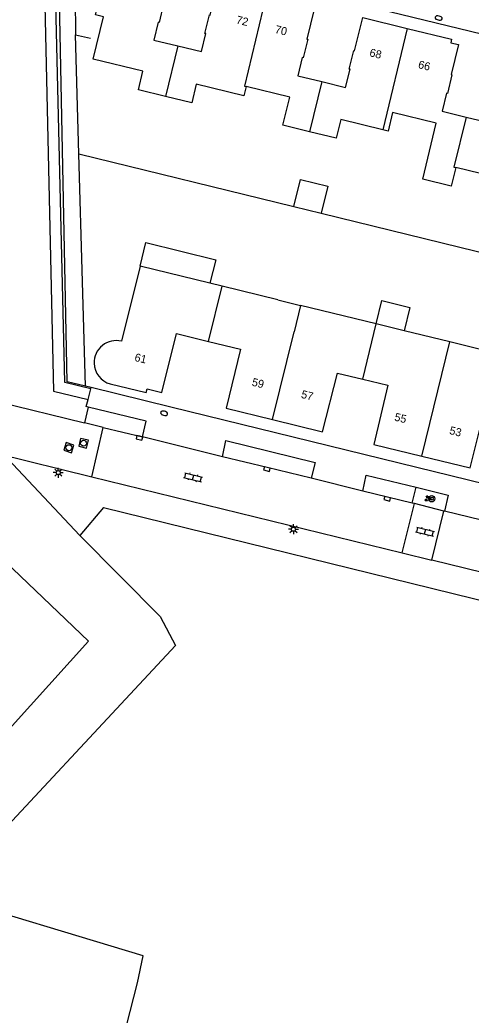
# Model space of a CAD drawing. Extents: x 125000 to 129004, y 397500 to 399008.
# Drawn here: x 126409.7 to 126466.2, y 397880.8 to 398005.2 of the extents above; entities that cross this region are included whole.
import ezdxf

# ---------------------------------------------------------------- set-up
doc = ezdxf.new("R2010")
doc.units = 0
for name, color, linetype in [('gg-afsc-erfafscheiding', 7, 'Continuous'), ('gg-anno-huisnummerreeks BGT', 7, 'Continuous'), ('gg-bbg-hoofdgebouw', 7, 'Continuous'), ('gg-bbg-luifel en loopbrug', 7, 'Continuous'), ('gg-bbg-tussenscheiding', 7, 'Continuous'), ('gg-knt-bronhoudergrens', 7, 'Continuous'), ('gg-knt-plantopografie kant verharding', 7, 'Continuous'), ('gg-knt-verharding', 7, 'Continuous'), ('gg-knt-verharding nz', 7, 'Continuous'), ('gt-grn-groengrens', 7, 'Continuous'), ('gt-grn-vlakafsluiter', 7, 'Continuous'), ('gt-symb-boom', 7, 'Continuous'), ('gt-symb-brandkraan', 7, 'Continuous'), ('gt-symb-groenvak', 7, 'Continuous'), ('gt-symb-klinker verharding', 7, 'Continuous'), ('gt-symb-kolk', 7, 'Continuous'), ('gt-symb-lichtmast', 7, 'Continuous'), ('gt-symb-rioolschacht', 7, 'Continuous')]:
    doc.layers.add(name, color=color, linetype=linetype)

# ---------------------------------------------------------------- blocks, each defined once
blk = doc.blocks.new('gt0-BR')
at = {"layer": 'gt-symb-brandkraan'}
for centre, radius, start, end in [((-0.24, 0), 0.206, 107.5669, 252.4331), ((0.6, -2.66), 3, 106.892, 107.5669), ((0, -0.69), 0.938, 73.108, 106.892), ((-0.6, -2.66), 3, 72.4331, 73.108), ((0.24, 0), 0.206, 287.567, 72.4331), ((0.6, 2.66), 3, 252.4331, 253.108), ((0, 0.69), 0.938, 253.108, 286.8921), ((-0.6, 2.66), 3, 286.8921, 287.567)]:
    blk.add_arc(centre, radius, start, end, dxfattribs=at)
blk = doc.blocks.new('gt0-RS')
at = {"layer": 'gt-symb-rioolschacht'}
blk.add_lwpolyline([(-0.5, -0.5), (0.5, -0.5), (0.5, 0.5), (-0.5, 0.5)], close=True, dxfattribs=at)
blk.add_circle((0, 0), 0.375, dxfattribs=at)
blk = doc.blocks.new('gt0-KOLK')
at = {"layer": 'gt-symb-kolk'}
blk.add_lwpolyline([(0, 0), (0.37, 0), (0.37, 0.4), (-0.38, 0.4), (-0.38, 0), (0, 0)], dxfattribs=at)
blk = doc.blocks.new('gt0-KL1')
at = {"layer": 'gt-symb-klinker verharding'}
for p, q in [((-1.15, 0.3), (1.15, 0.3)), ((-1, -0.3), (-1, 0.3)), ((-0.5, 0.3), (-0.5, 0.45)), ((0, -0.3), (0, 0.3)), ((0.5, 0.3), (0.5, 0.45)), ((1, -0.3), (1, 0.3)), ((-1.15, -0.3), (1.15, -0.3)), ((-0.5, -0.45), (-0.5, -0.3)), ((0.5, -0.45), (0.5, -0.3))]:
    blk.add_line(p, q, dxfattribs=at)
blk = doc.blocks.new('gt0-LMAST')
at = {"layer": 'gt-symb-lichtmast'}
for p, q in [((-0.18, 0.17), (-0.45, 0.44)), ((-0.01, 0.25), (-0.01, 0.62)), ((0.17, 0.17), (0.44, 0.44)), ((-0.26, 0), (-0.63, 0)), ((-0.18, -0.18), (-0.45, -0.45)), ((-0.01, -0.25), (-0.01, -0.63)), ((0.44, -0.45), (0.17, -0.18)), ((0.24, 0), (0.62, 0))]:
    blk.add_line(p, q, dxfattribs=at)
blk.add_circle((-0.01, 0), 0.25, dxfattribs=at)
blk = doc.blocks.new('gt0-GRVAK')
at = {"layer": 'gt-symb-groenvak'}
for p, q in [((-0.11, 0.19), (-0.23, 0.24)), ((-0.18, 0.15), (0.09, 0.15)), ((-0.09, 0.21), (-0.16, 0.32)), ((-0.05, 0.21), (-0.05, 0.39)), ((0, 0.21), (0.06, 0.32)), ((0.01, 0.19), (0.13, 0.24)), ((0.26, -0.05), (0.2, 0.06)), ((0.3, -0.05), (0.3, 0.13)), ((0.35, -0.05), (0.41, 0.06)), ((-0.24, -0.23), (-0.36, -0.18)), ((-0.32, -0.26), (-0.05, -0.26)), ((-0.23, -0.21), (-0.29, -0.09)), ((-0.18, -0.2), (-0.18, -0.02)), ((-0.14, -0.21), (-0.07, -0.09)), ((-0.12, -0.23), (0, -0.18)), ((0.24, -0.07), (0.12, -0.02)), ((0.17, -0.11), (0.44, -0.11)), ((0.37, -0.07), (0.49, -0.02))]:
    blk.add_line(p, q, dxfattribs=at)
blk = doc.blocks.new('gt0-BOOM')
at = {"layer": 'gt-symb-boom'}
for radius in [0.4, 0.2]:
    blk.add_circle((0, 0), radius, dxfattribs=at)

msp = doc.modelspace()

# ---------------------------------------------------------------- linework, layer by layer
at = {"layer": 'gg-afsc-erfafscheiding'}
for p, q in [((126417.11, 397988.44), (126416.68, 398003.33)), ((126416.68, 398003.33), (126418.55, 398002.89)), ((126417.11, 397988.44), (126444.02, 397981.86)), ((126447.42, 397981.02), (126484.77, 397971.88))]:
    msp.add_line(p, q, dxfattribs=at)
msp.add_lwpolyline([(126417.92, 397959.4), (126417.54, 397972.46), (126417.11, 397988.44)], dxfattribs=at)
at = {"layer": 'gg-bbg-hoofdgebouw'}
for p, q in [((126438.02, 397996.85), (126437.73, 397995.68)), ((126464.27, 397986.73), (126463.68, 397984.41)), ((126424.77, 397974.42), (126422.45, 397965.02)), ((126433.51, 397972.28), (126424.77, 397974.42)), ((126435.03, 397971.91), (126433.51, 397972.28)), ((126441.99, 397970.21), (126435.03, 397971.91)), ((126441.99, 397970.21), (126444.85, 397969.5)), ((126454.32, 397967.18), (126444.85, 397969.5)), ((126457.81, 397966.33), (126454.32, 397967.18)), ((126463.51, 397964.93), (126457.81, 397966.33)), ((126472.66, 397962.69), (126463.51, 397964.93))]:
    msp.add_line(p, q, dxfattribs=at)
for points in [[(126427.94, 397995.6), (126424.55, 397996.43), (126425.1, 397998.76), (126418.9, 398000.28), (126420.2, 398005.57), (126419.18, 398005.82), (126420.18, 398009.85), (126421.21, 398009.6), (126421.91, 398012.52), (126423.26, 398012.2), (126423.36, 398012.62), (126428.6, 398011.35), (126427.6, 398007.21), (126427.7, 398007.18), (126427.15, 398004.87), (126427.04, 398004.89), (126426.5, 398002.65), (126429.47, 398001.93)], [(126429.47, 398001.93), (126432.44, 398001.21), (126432.98, 398003.47), (126432.87, 398003.49), (126433.43, 398005.8), (126433.54, 398005.77), (126434.43, 398009.48), (126435.41, 398009.25), (126435.52, 398009.68), (126440.6, 398008.43)], [(126440.6, 398008.43), (126445.68, 398007.19), (126445.57, 398006.77), (126446.54, 398006.53), (126445.63, 398002.79), (126445.74, 398002.76), (126445.17, 398000.44), (126445.06, 398000.46), (126444.51, 397998.2), (126447.5, 397997.47)], [(126447.5, 397997.47), (126450.48, 397996.74), (126451.04, 397999), (126450.93, 397999.03), (126451.5, 398001.34), (126451.6, 398001.32), (126452.62, 398005.48), (126458.18, 398004.12)], [(126458.18, 398004.12), (126463.74, 398002.76), (126463.64, 398002.33), (126464.6, 398002.09), (126463.68, 397998.34), (126463.79, 397998.31), (126463.22, 397995.99), (126463.11, 397996.02), (126462.56, 397993.76), (126465.55, 397993.03)], [(126465.55, 397993.03), (126468.55, 397992.3), (126469.1, 397994.55), (126468.99, 397994.57), (126469.56, 397996.9), (126469.67, 397996.88), (126470.58, 398000.63), (126471.55, 398000.39), (126471.65, 398000.82), (126476.73, 397999.58)], [(126437.73, 397995.68), (126431.8, 397997.13), (126431.23, 397994.8), (126427.94, 397995.6)], [(126445.98, 397991.19), (126442.64, 397992.01), (126443.49, 397995.51), (126438.02, 397996.85)], [(126463.68, 397984.41), (126460.13, 397985.28), (126461.83, 397992.26), (126456.36, 397993.6), (126455.79, 397991.27), (126455.12, 397991.43)], [(126455.12, 397991.43), (126449.87, 397992.71), (126449.3, 397990.38), (126445.98, 397991.19)], [(126473.88, 397986.85), (126467.93, 397988.3), (126467.36, 397985.97), (126464.27, 397986.73)], [(126421.01, 397959.68), (126425.52, 397958.61), (126425.64, 397959.09), (126427.5, 397958.63), (126429.33, 397965.97), (126433.33, 397964.99)], [(126433.33, 397964.99), (126437.34, 397964.02), (126435.54, 397956.65), (126441.34, 397955.23)], [(126441.34, 397955.23), (126447.6, 397953.68), (126449.46, 397961.03), (126452.62, 397960.27)], [(126452.62, 397960.27), (126455.78, 397959.51), (126454.01, 397952.13), (126460.01, 397950.67)], [(126460.01, 397950.67), (126466.06, 397949.18), (126467.9, 397956.52), (126470.96, 397955.78)]]:
    msp.add_lwpolyline(points, dxfattribs=at)
for start, end in [(75.9037, 181.6433), (181.6226, 254.075)]:
    msp.add_arc((126421.77, 397962.34), 2.76, start, end, dxfattribs=at)
at = {"layer": 'gg-bbg-luifel en loopbrug'}
msp.add_line((126444.02, 397981.86), (126447.42, 397981.02), dxfattribs=at)
for points in [[(126444.02, 397981.86), (126444.84, 397985.24), (126448.24, 397984.42), (126447.42, 397981.02)], [(126424.77, 397974.42), (126425.48, 397977.34), (126434.23, 397975.2), (126433.51, 397972.28)], [(126454.32, 397967.18), (126455.03, 397970.1), (126458.53, 397969.24), (126457.81, 397966.33)]]:
    msp.add_lwpolyline(points, dxfattribs=at)
at = {"layer": 'gg-bbg-tussenscheiding'}
for p, q in [((126458.18, 398004.12), (126455.12, 397991.43)), ((126429.47, 398001.93), (126427.94, 397995.6)), ((126447.5, 397997.47), (126445.98, 397991.19)), ((126433.33, 397964.99), (126435.03, 397971.91)), ((126444.85, 397969.5), (126444.03, 397966.21)), ((126452.62, 397960.27), (126454.32, 397967.18)), ((126441.34, 397955.23), (126444.03, 397966.21)), ((126460.01, 397950.67), (126463.51, 397964.93))]:
    msp.add_line(p, q, dxfattribs=at)
for points in [[(126440.6, 398008.43), (126437.81, 397996.9), (126438.02, 397996.85)], [(126465.55, 397993.03), (126464.04, 397986.78), (126464.27, 397986.73)]]:
    msp.add_lwpolyline(points, dxfattribs=at)
at = {"layer": 'gg-knt-bronhoudergrens'}
msp.add_line((126420.18, 397944.24), (126417.22, 397940.74), dxfattribs=at)
for points in [[(126417.22, 397940.74), (126427.28, 397930.62), (126429.21, 397926.99), (126401.35, 397897.19), (126400.17, 397896.68)], [(126425.15, 397888.2), (126398.88, 397896.13), (126343.69, 397912.54), (126329.4, 397897.96), (126334.84, 397890.41), (126342.41, 397883.06)], [(126388.88, 397781.57), (126393.32, 397780.31), (126394.88, 397779.93), (126408.22, 397827.89), (126417.92, 397859.45), (126424.45, 397884.85), (126425.15, 397888.2)]]:
    msp.add_lwpolyline(points, dxfattribs=at)
at = {"layer": 'gg-knt-plantopografie kant verharding'}
for p, q in [((126256.94, 397994.13), (126417.82, 397954.83)), ((126255.52, 397988.3), (126418.73, 397948.06))]:
    msp.add_line(p, q, dxfattribs=at)
at = {"layer": 'gg-knt-verharding'}
for p, q in [((126417.28, 398015.7), (126579.42, 397976.05)), ((126418.25, 397957.76), (126418.62, 397959.09)), ((126418.62, 397959.09), (126418.65, 397959.22)), ((126418.28, 397956.78), (126417.82, 397954.83)), ((126420.15, 397954.26), (126417.82, 397954.83)), ((126418.73, 397948.06), (126420.15, 397954.26)), ((126435.06, 397950.59), (126425.05, 397953.06)), ((126418.73, 397948.06), (126457.55, 397938.56)), ((126452.65, 397946.29), (126446.17, 397947.9)), ((126458.79, 397944.78), (126459.3, 397946.77)), ((126457.55, 397938.56), (126459.08, 397944.73)), ((126459.08, 397944.73), (126458.79, 397944.78)), ((126462.76, 397943.8), (126459.08, 397944.73)), ((126461.28, 397937.67), (126462.76, 397943.8)), ((126462.85, 397943.77), (126462.76, 397943.8)), ((126471.08, 397941.78), (126462.85, 397943.77)), ((126457.55, 397938.56), (126461.28, 397937.67))]:
    msp.add_line(p, q, dxfattribs=at)
for points in [[(126412.65, 398016.35), (126413.94, 397958.76), (126418.25, 397957.76)], [(126418.62, 397959.09), (126415.34, 397959.88), (126414.03, 398015.99)], [(126518.59, 397934.74), (126428.62, 397956.79), (126418.65, 397959.22)], [(126418.28, 397956.78), (126418.01, 397956.86), (126418.25, 397957.76)], [(126425.05, 397953.06), (126425.54, 397955.05), (126418.28, 397956.78)], [(126435.06, 397950.59), (126435.49, 397952.6), (126446.66, 397949.88), (126446.17, 397947.9)], [(126452.65, 397946.29), (126453.05, 397948.28), (126459.3, 397946.77)], [(126459.3, 397946.77), (126463.3, 397945.8), (126462.85, 397943.77)], [(126653.58, 397890.6), (126642.67, 397893.29), (126528.84, 397921.13), (126461.28, 397937.67)]]:
    msp.add_lwpolyline(points, dxfattribs=at)
at = {"layer": 'gg-knt-verharding nz'}
for p, q in [((126420.15, 397954.26), (126425.05, 397953.06)), ((126458.79, 397944.78), (126452.65, 397946.29))]:
    msp.add_line(p, q, dxfattribs=at)
msp.add_lwpolyline([(126446.17, 397947.9), (126440.68, 397949.24), (126435.06, 397950.59)], dxfattribs=at)
at = {"layer": 'gt-grn-groengrens'}
for p, q in [((126416.53, 398015.89), (126416.68, 398003.33)), ((126417.22, 397940.74), (126384.88, 397975.06))]:
    msp.add_line(p, q, dxfattribs=at)
for points in [[(126417.92, 397959.4), (126415.66, 397959.95), (126414.53, 398015.86)], [(126396.12, 397897.9), (126396.12, 397903.01), (126418.33, 397927.54), (126386.98, 397957.42), (126382.67, 397952.36)]]:
    msp.add_lwpolyline(points, dxfattribs=at)
at = {"layer": 'gt-grn-vlakafsluiter'}
for p, q in [((126418.65, 397959.22), (126417.92, 397959.4)), ((126420.18, 397944.24), (126511.63, 397921.81))]:
    msp.add_line(p, q, dxfattribs=at)

# ---------------------------------------------------------------- block references
at = {"layer": 'gt-symb-boom'}
msp.add_blockref('gt0-BOOM', (126461.25, 397945.34), dxfattribs=at)
at = {"layer": 'gt-symb-brandkraan'}
for p, rotation in [((126462.12, 398005.41), 166.88085536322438), ((126427.77, 397956.02), 166.64465903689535)]:
    msp.add_blockref('gt0-BR', p, dxfattribs=dict(at, rotation=rotation))
at = {"layer": 'gt-symb-groenvak'}
msp.add_blockref('gt0-GRVAK', (126460.76, 397945.36), dxfattribs=at)
at = {"layer": 'gt-symb-klinker verharding'}
for p, rotation in [((126431.4, 397948), -13.772145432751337), ((126460.43, 397941.23), -13.827795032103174)]:
    msp.add_blockref('gt0-KL1', p, dxfattribs=dict(at, rotation=rotation))
at = {"layer": 'gt-symb-kolk'}
for p, rotation in [((126424.72, 397953.14), 166.4641436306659), ((126440.68, 397949.24), 166.2835306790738), ((126455.74, 397945.53), 166.04717668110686)]:
    msp.add_blockref('gt0-KOLK', p, dxfattribs=dict(at, rotation=rotation))
at = {"layer": 'gt-symb-lichtmast'}
for p in [(126414.53, 397948.6), (126443.96, 397941.52)]:
    msp.add_blockref('gt0-LMAST', p, dxfattribs=at)
at = {"layer": 'gt-symb-rioolschacht'}
for p, rotation in [((126415.85, 397951.72), -18.08532411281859), ((126417.69, 397952.28), -13.78766057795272)]:
    msp.add_blockref('gt0-RS', p, dxfattribs=dict(at, rotation=rotation))

# ---------------------------------------------------------------- texts
at = {"layer": 'gg-anno-huisnummerreeks BGT'}
for s, rotation, p in [('72', 346.3, (126436.72, 398004.75)), ('70', 346.3, (126441.57, 398003.56)), ('68', 346.2, (126453.4, 398000.66)), ('66', 346.2, (126459.49, 397999.17)), ('61', 346.6, (126424, 397962.57)), ('59', 346.2, (126438.68, 397959.48)), ('57', 346.2, (126444.85, 397957.96)), ('55', 346.2, (126456.52, 397955.12)), ('53', 346.2, (126463.4, 397953.44))]:
    msp.add_text(s, height=1, rotation=rotation, dxfattribs=at).set_placement(p)

doc.saveas('drawing.dxf')
